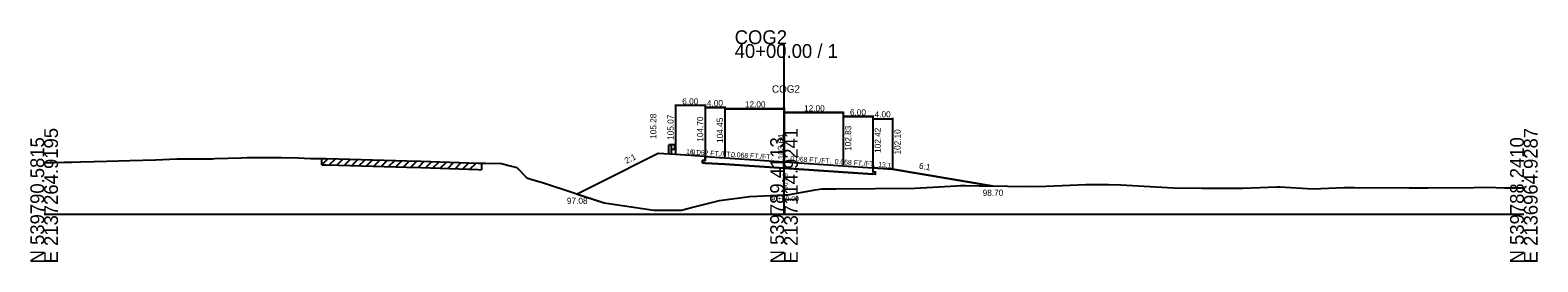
# Model space of a CAD drawing. Extents: x -13397 to 2303, y -10 to 39059.
# Drawn here: x 997.2 to 1302.8, y 19990.3 to 20037.3 of the extents above; entities that cross this region are included whole.
import ezdxf

# ---------------------------------------------------------------- set-up
doc = ezdxf.new("R2010")
doc.units = 0
for name, color, linetype in [('Level 1', 7, 'Continuous'), ('Level 5', 7, 'Continuous'), ('Level 53', 7, 'Continuous'), ('Level 54', 7, 'Continuous'), ('Level 55', 7, 'Continuous'), ('Level 7', 7, 'Continuous'), ('RD_GPK_XS_Cell', 7, 'Continuous'), ('RD_XS_EwShp', 7, 'Continuous'), ('RD_XS_ExGround', 7, 'Continuous'), ('RD_XS_ExPaveRet', 7, 'Continuous'), ('RD_XS_Pave', 7, 'Continuous'), ('RD_XS_TX_Baseline', 7, 'Continuous'), ('RD_XS_TX_Elev_EX', 7, 'Continuous'), ('RD_XS_TX_Elev_PR', 7, 'Continuous'), ('RD_XS_TX_Station', 7, 'Continuous')]:
    doc.layers.add(name, color=color, linetype=linetype)

msp = doc.modelspace()

# ---------------------------------------------------------------- linework, layer by layer
at = {"layer": 'Level 1'}
for p, q in [((1126.66, 20012.07), (1126.66, 20014.06)), ((1127.22, 20014.06), (1126.66, 20014.06)), ((1127.22, 20012.07), (1127.22, 20014.06)), ((1127.77, 20014.06), (1127.22, 20014.06)), ((1127.77, 20013.08), (1127.22, 20013.08)), ((1127.77, 20014.06), (1127.77, 20013.08)), ((1127.85, 20013.98), (1127.77, 20013.99)), ((1127.85, 20013.16), (1127.77, 20013.14)), ((1127.84, 20013.65), (1127.84, 20013.49)), ((1127.98, 20013.88), (1127.86, 20013.98)), ((1127.98, 20013.78), (1127.86, 20013.69)), ((1127.98, 20013.36), (1127.86, 20013.45)), ((1127.98, 20013.25), (1127.86, 20013.16))]:
    msp.add_line(p, q, dxfattribs=at)
for centre, radius, start, end in [((1127.91, 20013.65), 0.0651, 135, 180), ((1127.91, 20013.49), 0.0651, 180, 237.0105), ((1127.85, 20013.96), 0.026, 50.9495, 90), ((1127.85, 20013.18), 0.026, 270, 309.0504), ((1127.93, 20013.83), 0.0651, 309.0337, 50.9664), ((1127.93, 20013.3), 0.0651, 309.0337, 50.9664)]:
    msp.add_arc(centre, radius, start, end, dxfattribs=at)
at = {"layer": 'Level 5'}
for p, q in [((1133.5, 20010.9), (1133.5, 20010.4)), ((1134, 20010.87), (1133.5, 20010.9)), ((1133.5, 20010.4), (1134, 20010.37)), ((1134, 20011.7), (1134, 20010.87)), ((1138, 20010.12), (1134, 20010.37)), ((1138, 20010.12), (1134, 20010.37)), ((1138, 20010.12), (1134, 20010.37)), ((1134, 20010.37), (1138, 20010.12)), ((1150, 20009.31), (1138, 20010.12)), ((1150, 20009.31), (1138, 20010.12)), ((1150, 20009.31), (1138, 20010.12)), ((1138, 20010.12), (1150, 20009.31)), ((1138, 20010.12), (1150, 20009.31)), ((1162, 20008.49), (1150, 20009.31)), ((1162, 20008.49), (1150, 20009.31)), ((1150, 20009.31), (1162, 20008.49)), ((1150, 20009.31), (1162, 20008.49)), ((1150, 20009.31), (1162, 20008.49)), ((1168, 20008.09), (1162, 20008.49)), ((1162, 20008.49), (1168, 20008.09)), ((1162, 20008.49), (1168, 20008.09)), ((1162, 20008.49), (1168, 20008.09)), ((1168, 20009.42), (1168, 20008.59)), ((1168, 20008.59), (1168.5, 20008.55)), ((1168.5, 20008.05), (1168, 20008.09)), ((1168.5, 20008.55), (1168.5, 20008.05))]:
    msp.add_line(p, q, dxfattribs=at)
at = {"layer": 'Level 54'}
for p, q in [((1128, 20022.22), (1128, 20012.27)), ((1134, 20022.22), (1134, 20011.9)), ((1134, 20022.02), (1128, 20022.02)), ((1134, 20021.85), (1134, 20011.9)), ((1134, 20021.85), (1134, 20011.9)), ((1134, 20021.85), (1134, 20011.9)), ((1134, 20021.85), (1134, 20011.9)), ((1134, 20021.65), (1138, 20021.65)), ((1134, 20021.65), (1138, 20021.65)), ((1134, 20021.65), (1138, 20021.65)), ((1138, 20021.65), (1134, 20021.65)), ((1138, 20021.85), (1138, 20011.65)), ((1138, 20021.85), (1138, 20011.65)), ((1138, 20021.85), (1138, 20011.65)), ((1138, 20021.85), (1138, 20011.65)), ((1138, 20021.6), (1138, 20011.65)), ((1138, 20021.6), (1138, 20011.65)), ((1138, 20021.6), (1138, 20011.65)), ((1138, 20021.6), (1138, 20011.65)), ((1138, 20021.6), (1138, 20011.65)), ((1138, 20021.4), (1150, 20021.4)), ((1138, 20021.4), (1150, 20021.4)), ((1138, 20021.4), (1150, 20021.4)), ((1150, 20021.4), (1138, 20021.4)), ((1150, 20021.4), (1138, 20021.4)), ((1150, 20021.6), (1150, 20010.84)), ((1150, 20021.6), (1150, 20010.84)), ((1150, 20021.6), (1150, 20010.84)), ((1150, 20021.6), (1150, 20010.84)), ((1150, 20021.6), (1150, 20010.84)), ((1150, 20020.79), (1150, 20010.84)), ((1150, 20020.79), (1150, 20010.84)), ((1150, 20020.79), (1150, 20010.84)), ((1150, 20020.79), (1150, 20010.84)), ((1150, 20020.79), (1150, 20010.84)), ((1150, 20020.59), (1162, 20020.59)), ((1150, 20020.59), (1162, 20020.59)), ((1162, 20020.59), (1150, 20020.59)), ((1162, 20020.59), (1150, 20020.59)), ((1162, 20020.59), (1150, 20020.59)), ((1162, 20020.79), (1162, 20010.03)), ((1162, 20020.79), (1162, 20010.03)), ((1162, 20020.79), (1162, 20010.03)), ((1162, 20020.79), (1162, 20010.03)), ((1162, 20020.79), (1162, 20010.03)), ((1162, 20019.98), (1162, 20010.03)), ((1162, 20019.98), (1162, 20010.03)), ((1162, 20019.98), (1162, 20010.03)), ((1162, 20019.98), (1162, 20010.03)), ((1162, 20019.78), (1168, 20019.78)), ((1168, 20019.78), (1162, 20019.78)), ((1168, 20019.78), (1162, 20019.78)), ((1168, 20019.78), (1162, 20019.78)), ((1168, 20019.98), (1168, 20009.62)), ((1168, 20019.98), (1168, 20009.62)), ((1168, 20019.98), (1168, 20009.62)), ((1168, 20019.98), (1168, 20009.62)), ((1168, 20019.57), (1168, 20009.62)), ((1168, 20019.37), (1172, 20019.37)), ((1172, 20019.57), (1172, 20009.3))]:
    msp.add_line(p, q, dxfattribs=at)
at = {"layer": 'Level 7'}
for p, q in [((1124.5, 20012.28), (1112.5, 20006.28)), ((1128, 20012.07), (1124.5, 20012.28)), ((1134, 20011.7), (1128, 20012.07)), ((1168, 20009.42), (1172, 20009.1)), ((1172, 20009.1), (1184, 20007.1)), ((1184, 20007.1), (1192.38, 20005.7)), ((1112.5, 20006.28), (1108.09, 20004.08))]:
    msp.add_line(p, q, dxfattribs=at)
at = {"layer": 'RD_GPK_XS_Cell'}
for p, q in [((1150, 20000), (1150, 20034.5)), ((1000, 20000), (1150, 20000)), ((1150, 20000), (1300, 20000))]:
    msp.add_line(p, q, dxfattribs=at)
at = {"layer": 'RD_XS_EwShp'}
msp.add_lwpolyline([(1157.64, 20005.13), (1160.52, 20005.16), (1176.55, 20005.25), (1184.97, 20005.74), (1185.81, 20005.8), (1186.78, 20005.78), (1192.38, 20005.7), (1184, 20007.1), (1172, 20009.1), (1168, 20009.42), (1168, 20008.59), (1168.5, 20008.55), (1168.5, 20008.05), (1168, 20008.09), (1162, 20008.49), (1150, 20009.31), (1138, 20010.12), (1134, 20010.37), (1133.5, 20010.4), (1133.5, 20010.9), (1134, 20010.87), (1134, 20011.7), (1128, 20012.07), (1124.5, 20012.28), (1112.5, 20006.28), (1108.09, 20004.08), (1113.54, 20002.28), (1123.64, 20000.78), (1128.29, 20000.79), (1129.25, 20000.79), (1131.23, 20001.35), (1136.92, 20002.79), (1143.1, 20003.59), (1150, 20003.89), (1150.8, 20003.93), (1156.35, 20004.9)], close=True, dxfattribs=at)
at = {"layer": 'RD_XS_ExGround'}
for p, q in [((1000, 20010.43), (1004.08, 20010.53)), ((1004.08, 20010.53), (1005.63, 20010.54)), ((1005.63, 20010.54), (1007.44, 20010.6)), ((1007.44, 20010.6), (1012.73, 20010.77)), ((1012.73, 20010.77), (1017.36, 20010.9)), ((1017.36, 20010.9), (1022.55, 20011.05)), ((1022.55, 20011.05), (1026.96, 20011.19)), ((1026.96, 20011.19), (1029.12, 20011.19)), ((1029.12, 20011.19), (1032.08, 20011.2)), ((1032.08, 20011.2), (1034.1, 20011.2)), ((1034.1, 20011.2), (1034.61, 20011.31)), ((1034.61, 20011.31), (1039.91, 20011.45)), ((1039.91, 20011.45), (1041.14, 20011.48)), ((1041.14, 20011.48), (1043.93, 20011.5)), ((1043.93, 20011.5), (1048.13, 20011.48)), ((1048.13, 20011.48), (1051.45, 20011.42)), ((1051.45, 20011.42), (1054.03, 20011.32)), ((1054.03, 20011.32), (1056.31, 20011.31)), ((1056.31, 20011.31), (1057.09, 20011.29)), ((1057.09, 20011.29), (1059.68, 20011.2)), ((1059.68, 20011.2), (1073.56, 20010.83)), ((1073.56, 20010.83), (1076.36, 20010.75)), ((1076.36, 20010.75), (1088, 20010.34)), ((1088, 20010.34), (1088.66, 20010.32)), ((1088.66, 20010.32), (1089.54, 20010.31)), ((1089.54, 20010.31), (1092.69, 20010.29)), ((1092.69, 20010.29), (1094.19, 20009.88)), ((1094.19, 20009.88), (1095.85, 20009.46)), ((1095.85, 20009.46), (1097.89, 20007.34)), ((1097.89, 20007.34), (1098.84, 20007)), ((1098.84, 20007), (1101.05, 20006.39)), ((1101.05, 20006.39), (1113.54, 20002.28)), ((1143.1, 20003.59), (1150, 20003.89)), ((1150, 20003.89), (1150.8, 20003.93)), ((1150.8, 20003.93), (1156.35, 20004.9)), ((1156.35, 20004.9), (1157.64, 20005.13)), ((1157.64, 20005.13), (1160.52, 20005.16)), ((1160.52, 20005.16), (1176.55, 20005.25)), ((1176.55, 20005.25), (1184.97, 20005.74)), ((1184.97, 20005.74), (1185.81, 20005.8)), ((1185.81, 20005.8), (1186.78, 20005.78)), ((1186.78, 20005.78), (1199.64, 20005.6)), ((1199.64, 20005.6), (1203.16, 20005.67)), ((1203.16, 20005.67), (1211.19, 20006)), ((1211.19, 20006), (1215.76, 20006.03)), ((1215.76, 20006.03), (1218.3, 20005.95)), ((1218.3, 20005.95), (1228.99, 20005.34)), ((1228.99, 20005.34), (1234.7, 20005.29)), ((1234.7, 20005.29), (1243.01, 20005.26)), ((1243.01, 20005.26), (1249.89, 20005.51)), ((1249.89, 20005.51), (1250.52, 20005.51)), ((1250.52, 20005.51), (1257.25, 20005.1)), ((1257.25, 20005.1), (1263.63, 20005.38)), ((1263.63, 20005.38), (1265.67, 20005.41)), ((1265.67, 20005.41), (1276.74, 20005.31)), ((1276.74, 20005.31), (1278.5, 20005.33)), ((1278.5, 20005.33), (1280.6, 20005.36)), ((1280.6, 20005.36), (1289.84, 20005.42)), ((1289.84, 20005.42), (1292.57, 20005.44)), ((1292.57, 20005.44), (1296.11, 20005.36)), ((1296.11, 20005.36), (1300, 20005.33)), ((1113.54, 20002.28), (1123.64, 20000.78)), ((1123.64, 20000.78), (1128.29, 20000.79)), ((1128.29, 20000.79), (1129.25, 20000.79)), ((1129.25, 20000.79), (1131.23, 20001.35)), ((1131.23, 20001.35), (1136.92, 20002.79)), ((1136.92, 20002.79), (1143.1, 20003.59))]:
    msp.add_line(p, q, dxfattribs=at)
at = {"layer": 'RD_XS_ExPaveRet'}
for p, q in [((1056.31, 20010.01), (1056.31, 20011.31)), ((1056.31, 20010.01), (1057.57, 20011.28)), ((1056.31, 20010.01), (1057.09, 20009.99)), ((1057.09, 20009.99), (1059.68, 20009.9)), ((1057.81, 20009.97), (1059.07, 20011.22)), ((1059.31, 20009.91), (1060.58, 20011.17)), ((1060.81, 20009.87), (1062.08, 20011.13)), ((1062.31, 20009.83), (1063.58, 20011.09)), ((1063.81, 20009.79), (1065.08, 20011.05)), ((1065.31, 20009.75), (1066.58, 20011.01)), ((1066.81, 20009.71), (1068.08, 20010.97)), ((1068.31, 20009.67), (1069.58, 20010.93)), ((1069.81, 20009.63), (1071.08, 20010.89)), ((1071.31, 20009.59), (1072.58, 20010.85)), ((1072.81, 20009.55), (1074.08, 20010.81)), ((1074.31, 20009.51), (1075.58, 20010.77)), ((1075.81, 20009.47), (1077.07, 20010.73)), ((1077.31, 20009.42), (1078.57, 20010.67)), ((1078.81, 20009.36), (1080.07, 20010.62)), ((1080.32, 20009.31), (1081.57, 20010.57)), ((1081.82, 20009.26), (1083.07, 20010.51)), ((1083.32, 20009.21), (1084.57, 20010.46)), ((1084.82, 20009.15), (1086.07, 20010.41)), ((1086.32, 20009.1), (1087.57, 20010.35)), ((1088.66, 20010.32), (1088.66, 20009.02)), ((1059.68, 20009.9), (1073.56, 20009.53)), ((1073.56, 20009.53), (1076.36, 20009.45)), ((1076.36, 20009.45), (1088, 20009.04)), ((1088, 20009.04), (1088.66, 20009.02))]:
    msp.add_line(p, q, dxfattribs=at)
at = {"layer": 'RD_XS_Pave'}
for p, q in [((1134, 20011.7), (1138, 20011.45)), ((1138, 20011.45), (1150, 20010.64)), ((1150, 20010.64), (1162, 20009.83)), ((1162, 20009.83), (1168, 20009.42))]:
    msp.add_line(p, q, dxfattribs=at)

# ---------------------------------------------------------------- texts
at = {"layer": 'Level 53'}
for s, rotation, p in [('105.28', 90, (1124.12, 20015.28)), ('105.07', 90, (1127.62, 20015.07)), ('104.70', 90, (1133.62, 20014.7)), ('104.45', 90, (1137.63, 20014.45)), ('104.45', 90, (1137.63, 20014.45)), ('104.45', 90, (1137.63, 20014.45)), ('102.83', 90, (1163.62, 20012.83)), ('102.83', 90, (1163.62, 20012.83)), ('102.83', 90, (1163.62, 20012.83)), ('102.42', 90, (1169.63, 20012.42)), ('102.10', 90, (1173.63, 20012.1)), ('2:1', 26.5651, (1118.05, 20010.18)), ('6:1', 350.5377, (1177.3, 20009.23))]:
    msp.add_text(s, height=1.25, rotation=rotation, dxfattribs=at).set_placement(p)
for s, p in [('98.70', (1190.28, 20003.7)), ('97.08', (1105.99, 20002.08))]:
    msp.add_text(s, height=1.25, dxfattribs=at).set_placement(p)
at = {"layer": 'Level 54'}
for s, p in [('6.00', (1129.37, 20022.27)), ('4.00', (1134.37, 20021.9)), ('4.00', (1134.37, 20021.9)), ('4.00', (1134.37, 20021.9)), ('4.00', (1134.37, 20021.9)), ('12.00', (1142.07, 20021.65)), ('12.00', (1142.07, 20021.65)), ('12.00', (1142.07, 20021.65)), ('12.00', (1142.07, 20021.65)), ('12.00', (1142.07, 20021.65)), ('12.00', (1154.07, 20020.84)), ('12.00', (1154.07, 20020.84)), ('12.00', (1154.07, 20020.84)), ('12.00', (1154.07, 20020.84)), ('12.00', (1154.07, 20020.84)), ('6.00', (1163.37, 20020.03)), ('6.00', (1163.37, 20020.03)), ('6.00', (1163.37, 20020.03)), ('6.00', (1163.37, 20020.03)), ('4.00', (1168.37, 20019.62))]:
    msp.add_text(s, height=1.25, dxfattribs=at).set_placement(p)
at = {"layer": 'Level 55'}
for s, rotation, p in [('16:1', 356.4772, (1130.12, 20012.19)), ('0.062 FT./FT.', 356.4772, (1131.19, 20012.12)), ('0.062 FT./FT.', 356.4772, (1131.19, 20012.12)), ('0.062 FT./FT.', 356.4772, (1131.19, 20012.12)), ('0.062 FT./FT.', 356.4772, (1131.19, 20012.12)), ('0.068 FT./FT.', 356.1265, (1139.25, 20011.62)), ('0.068 FT./FT.', 356.1265, (1139.25, 20011.62)), ('0.068 FT./FT.', 356.1265, (1139.25, 20011.62)), ('0.068 FT./FT.', 356.1265, (1139.25, 20011.62)), ('0.068 FT./FT.', 356.1265, (1139.25, 20011.62)), ('0.068 FT./FT.', 356.1265, (1151.25, 20010.81)), ('0.068 FT./FT.', 356.1265, (1151.25, 20010.81)), ('0.068 FT./FT.', 356.1265, (1151.25, 20010.81)), ('0.068 FT./FT.', 356.1265, (1151.25, 20010.81)), ('0.068 FT./FT.', 356.1265, (1151.25, 20010.81)), ('0.068 FT./FT.', 356.1265, (1160.25, 20010.2)), ('0.068 FT./FT.', 356.1265, (1160.25, 20010.2)), ('0.068 FT./FT.', 356.1265, (1160.25, 20010.2)), ('0.068 FT./FT.', 356.1265, (1160.25, 20010.2)), ('13:1', 355.4261, (1169.07, 20009.59))]:
    msp.add_text(s, height=1, rotation=rotation, dxfattribs=at).set_placement(p)
at = {"layer": 'RD_GPK_XS_Cell'}
for s, p in [('40+00.00 / 1', (1140, 20031.7)), ('COG2', (1140, 20034.5))]:
    msp.add_text(s, height=2.8, dxfattribs=at).set_placement(p)
for s, p in [('E 2137264.9195', (1002.8, 19990)), ('E 2137114.9241', (1152.8, 19990)), ('E 2136964.9287', (1302.8, 19990)), ('N 539790.5815', (1000, 19990)), ('N 539789.4113', (1150, 19990)), ('N 539788.2410', (1300, 19990))]:
    msp.add_text(s, height=2.8, rotation=90, dxfattribs=at).set_placement(p)
at = {"layer": 'RD_XS_TX_Baseline'}
msp.add_text('COG2', height=1.5, dxfattribs=at).set_placement((1147.55, 20024.64))
at = {"layer": 'RD_XS_TX_Elev_EX'}
msp.add_text('96.89', height=1, rotation=90, dxfattribs=at).set_placement((1150.75, 20004.89))
at = {"layer": 'RD_XS_TX_Elev_PR'}
msp.add_text(' 103.64', height=1.25, rotation=90, dxfattribs=at).set_placement((1150, 20010.64))
at = {"layer": 'RD_XS_TX_Station'}
msp.add_text('40+00.00', height=1, dxfattribs=at).set_placement((1147.21, 20002.64))

doc.saveas('drawing.dxf')
